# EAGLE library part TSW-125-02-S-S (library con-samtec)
THROUGH-HOLE .025" SQ POST HEADER Source: Samtec TSW.pdf
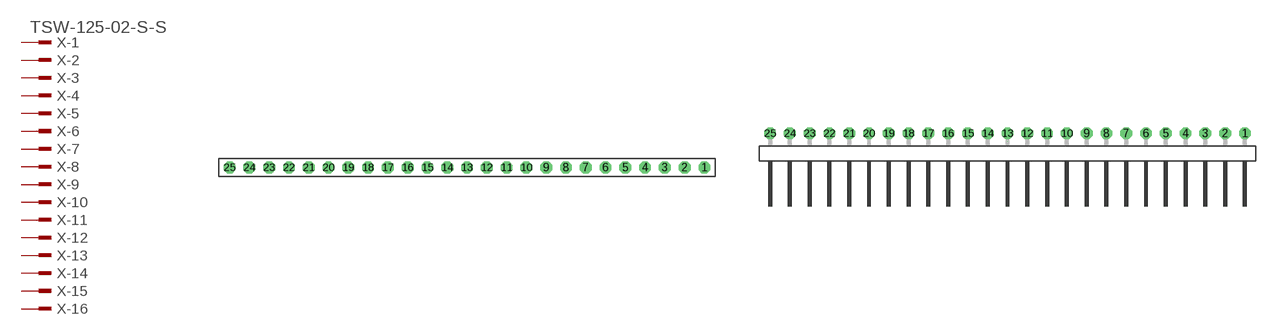
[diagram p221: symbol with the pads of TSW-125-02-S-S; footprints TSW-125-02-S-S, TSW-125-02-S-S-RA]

Designator prefix X; gates -1=MPINV -2=MPIN -3=MPIN -4=MPIN -5=MPIN -6=MPIN -7=MPIN -8=MPIN -9=MPIN -10=MPIN -11=MPIN -12=MPIN -13=MPIN -14=MPIN -15=MPIN -16=MPIN -17=MPIN -18=MPIN -19=MPIN -20=MPIN -21=MPIN -22=MPIN -23=MPIN -24=MPIN -25=MPIN

## TSW-125-02-S-S (OC_FARNELL: unknown; OC_NEWARK: unknown)  [TSW-125-02-S-S]
1  -1:1  pas
2  -2:1  pas
3  -3:1  pas
4  -4:1  pas
5  -5:1  pas
6  -6:1  pas
7  -7:1  pas
8  -8:1  pas
9  -9:1  pas
10  -10:1  pas
11  -11:1  pas
12  -12:1  pas
13  -13:1  pas
14  -14:1  pas
15  -15:1  pas
16  -16:1  pas
17  -17:1  pas
18  -18:1  pas
19  -19:1  pas
20  -20:1  pas
21  -21:1  pas
22  -22:1  pas
23  -23:1  pas
24  -24:1  pas
25  -25:1  pas

## TSW-125-02-S-S-RA (OC_FARNELL: unknown; OC_NEWARK: unknown)  [TSW-125-02-S-S-RA]
Pads as for TSW-125-02-S-S

## Footprint TSW-125-02-S-S (pad centres in mm)
THROUGH-HOLE .025" SQ POST HEADER Source: Samtec TSW.pdf
drill 1 pad 1.5 octagon: 1 30.48,0; 2 27.94,0; 3 25.4,0; 4 22.86,0; 5 20.32,0; 6 17.78,0; 7 15.24,0; 8 12.7,0; 9 10.16,0; 10 7.62,0; 11 5.08,0; 12 2.54,0; 13 0,0; 14 -2.54,0; 15 -5.08,0; 16 -7.62,0; 17 -10.16,0; 18 -12.7,0; 19 -15.24,0; 20 -17.78,0; 21 -20.32,0; 22 -22.86,0; 23 -25.4,0; 24 -27.94,0; 25 -30.48,0

## Footprint TSW-125-02-S-S-RA (pad centres in mm)
THROUGH-HOLE .025" SQ POST HEADER Source: Samtec TSW.pdf
drill 1 pad 1.5 octagon: 1 30.48,1.524; 2 27.94,1.524; 3 25.4,1.524; 4 22.86,1.524; 5 20.32,1.524; 6 17.78,1.524; 7 15.24,1.524; 8 12.7,1.524; 9 10.16,1.524; 10 7.62,1.524; 11 5.08,1.524; 12 2.54,1.524; 13 0,1.524; 14 -2.54,1.524; 15 -5.08,1.524; 16 -7.62,1.524; 17 -10.16,1.524; 18 -12.7,1.524; 19 -15.24,1.524; 20 -17.78,1.524; 21 -20.32,1.524; 22 -22.86,1.524; 23 -25.4,1.524; 24 -27.94,1.524; 25 -30.48,1.524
